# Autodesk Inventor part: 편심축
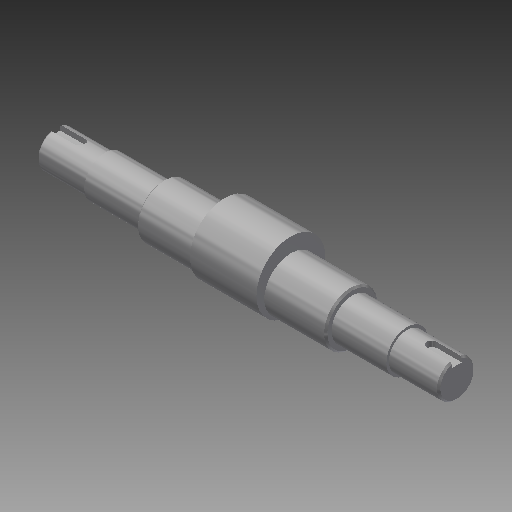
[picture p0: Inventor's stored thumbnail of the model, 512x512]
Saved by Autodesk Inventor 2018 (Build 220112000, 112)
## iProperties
Created: 2015-10
Part Number: 편심축
Document SubType Name: Modeling
Designer: mdu
Density: 1 g/cm^3
Material: 강철, 연강
Mass: 168.947 g
Surface Area: 248.524 cm^2
Volume: 168.947 cm^3
Appearance: 강철
Author: mdu
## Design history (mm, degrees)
sketch "스케치1"
  geometry: L1 (-20.5, -41.331)-(-20.5, 32.669) reference; L2 (7.5, -30.031)-(7.5, 21.369) reference; L3 (135.5, -30.331)-(135.5, 21.669) reference; L4 (121.5, 21.369)-(121.5, -30.031) reference; L5 (184.5, -4.331)-(-57.5, -4.331); L6 (184.5, -4.331)-(184.5, 6.669); L7 (154.5, 8.169)-(121.5, 8.169); L8 (121.5, 8.169)-(121.5, 11.669); L9 (121.5, 11.669)-(7.5, 11.669); L10 (7.5, 11.669)-(7.5, 8.169); L11 (7.5, 8.169)-(-27.5, 8.169); L12 (-27.5, 8.169)-(-27.5, 6.669); L13 (-27.5, 6.669)-(-57.5, 6.669); L14 (-57.5, 6.669)-(-57.5, -4.331); L15 (154.5, 8.169)-(154.5, 6.669); L16 (154.5, 6.669)-(184.5, 6.669); C1 r 32.5 at (64.5, -4.331) reference; 1 further point
  constraints: 24 end point, 8 perpendicular, 5 point on line, 3 parallel, 2 collinear
  dimensions: "d1" = 25 diameter of L11 L5; "d2" = 32 diameter of L9 L5; "d3" = 22 diameter of L13 L5; "d4" = 35 distance of L10.end L11.end; "d5" = 30 distance of L12.end L13.end; "d15" = 33 distance of L7.start L7.end; "d26" = 30 distance of L15.end L6.end
revolve "회전1" sketch "스케치1" stored, may be unused: angle "d6" = 90 deg
node "작업 평면1"
sketch "스케치2"
  geometry: C1 r 16 at (0, 0) reference; C2 r 20.75 at (0, 4)
  constraints: 1 centre point, 1 vertical alignment
  dimensions: "d34" = 4 distance of C2.centre C1.centre; "d35" = 41.5 diameter of C2
extrude "돌출1" join sketch "스케치2" stored distance "d9" = 40; taper "d10" = 0 deg
chamfer "모따기1" distance "d11" = 1; stored, may be unused: second distance "d12" = 2, angle "d13" = 45 deg
node "작업 평면2"
sketch "스케치3"
  geometry: L1 (-15, -10)-(-15, 10) reference; L2 (-15, 3)-(0, 3); L3 (0, -3)-(-15, -3); A1 r 3 centre (0, 0) between (0, -3) and (0, 3); 2 further points
  constraints: 4 end point, 2 perpendicular, 2 point on circle, 2 point on line, 2 tangent, 1 centre point, 1 horizontal alignment, 1 midpoint
  dimensions: "d16" = 18 dimension on A1 L1; "d17" = 6 distance between parallel lines of L3 L2
extrude "돌출2" cut sketch "스케치3" distance "d18" = 3.5; taper "d19" = 0 deg
node "작업 평면3"
node "솔리드1"
mirror "대칭1"
node "참조1"
node "참조2"
node "참조3"
node "참조4"
node "참조5"
other parameters: "d30" = 35
